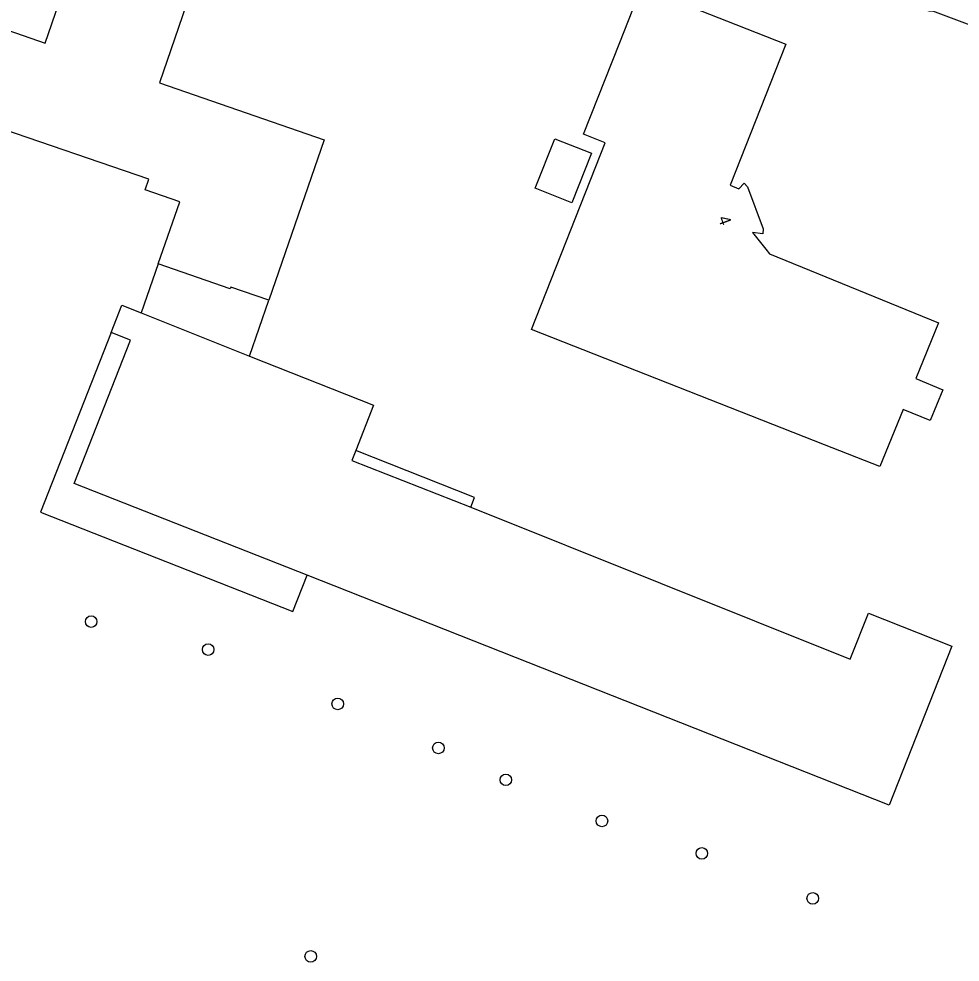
# Model space of a CAD drawing. Extents: x 160664 to 161506, y 382245 to 383288.
# Drawn here: x 161158.3 to 161237.8, y 382754.5 to 382834.1 of the extents above; entities that cross this region are included whole.
import ezdxf

# ---------------------------------------------------------------- set-up
doc = ezdxf.new("R2010")
doc.units = 0
for name, color, linetype in [('IMGEO_Boom', 7, 'Continuous'), ('IMGEO_Pand', 7, 'Continuous'), ('IMGEO_Pand_nummerreeks', 7, 'Continuous'), ('IMGEO_Pand_overbouw', 7, 'Continuous'), ('IMGEO_Voetpad_open', 7, 'Continuous')]:
    doc.layers.add(name, color=color, linetype=linetype)

msp = doc.modelspace()

# ---------------------------------------------------------------- linework, layer by layer
at = {"layer": 'IMGEO_Boom'}
for centre in [(161164.399, 382783.227), (161174.285, 382780.867), (161185.219, 382776.279), (161193.724, 382772.557), (161199.42, 382769.87), (161207.538, 382766.396), (161215.972, 382763.659), (161225.335, 382759.857), (161182.942, 382754.962)]:
    msp.add_circle(centre, 0.489, dxfattribs=at)
at = {"layer": 'IMGEO_Pand'}
for points in [[(161179.142, 382854.897), (161170.186, 382828.718), (161184.075, 382823.91), (161179.403, 382810.366), (161176.183, 382811.477), (161176.134, 382811.335), (161170.065, 382813.429), (161171.878, 382818.686), (161168.975, 382819.679), (161169.285, 382820.585), (161155.927, 382825.155)], [(161146.659, 382836.881), (161158.651, 382832.727), (161160.516, 382832.089), (161162.531, 382837.979)], [(161201.577, 382807.889), (161207.801, 382823.654), (161205.969, 382824.378), (161209.036, 382832.145), (161210.872, 382836.795)], [(161213.235, 382835.862), (161218.046, 382833.963), (161223.053, 382831.986), (161218.349, 382820.078), (161219.091, 382819.776), (161219.55, 382820.255), (161219.836, 382819.956), (161221.144, 382816.389), (161221.118, 382815.964), (161220.235, 382816.079), (161221.369, 382814.681), (161221.685, 382814.292), (161235.954, 382808.452), (161234.03, 382803.751), (161236.325, 382802.811), (161235.257, 382800.201), (161232.962, 382801.141), (161230.992, 382796.328), (161226.339, 382798.157), (161201.577, 382807.889)], [(161201.889, 382819.817), (161203.542, 382824.003), (161206.648, 382822.776), (161204.996, 382818.591), (161201.889, 382819.817)], [(161182.636, 382787.155), (161162.959, 382794.885), (161167.722, 382806.997), (161166.099, 382807.652), (161166.999, 382809.942), (161168.637, 382809.291), (161177.779, 382805.658), (161188.239, 382801.501), (161186.741, 382797.691), (161186.412, 382796.844), (161196.472, 382792.888), (161228.496, 382780.058), (161230.033, 382783.936), (161237.077, 382781.143), (161231.783, 382767.732), (161182.636, 382787.155)]]:
    msp.add_lwpolyline(points, dxfattribs=at)
at = {"layer": 'IMGEO_Pand_overbouw'}
for points in [[(161170.065, 382813.429), (161168.637, 382809.291), (161177.779, 382805.658), (161179.403, 382810.366), (161176.183, 382811.477), (161176.134, 382811.335)], [(161166.099, 382807.652), (161160.125, 382792.461), (161181.425, 382784.086), (161182.636, 382787.155), (161162.959, 382794.885), (161167.722, 382806.997)], [(161186.741, 382797.691), (161186.412, 382796.844), (161196.472, 382792.888), (161196.786, 382793.71)]]:
    msp.add_lwpolyline(points, close=True, dxfattribs=at)
at = {"layer": 'IMGEO_Voetpad_open'}
msp.add_lwpolyline([(161247.543, 382790.576), (161243.275, 382831.841), (161235.463, 382834.768), (161235.153, 382834.791), (161226.716, 382838.135), (161227.393, 382839.873), (161225.76, 382840.503), (161226.068, 382841.467)], dxfattribs=at)

# ---------------------------------------------------------------- texts
at = {"layer": 'IMGEO_Pand_nummerreeks'}
msp.add_text('4', height=1, rotation=290.13772, dxfattribs=at).set_placement((161217.316, 382817.302))

doc.saveas('drawing.dxf')
